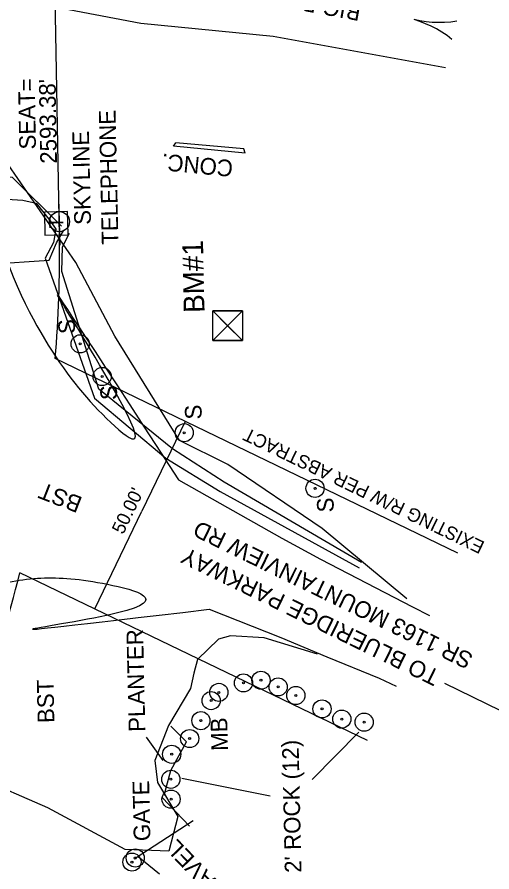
# Model space of a CAD drawing. Extents: x 1417249 to 1417944, y 999313 to 1000321.
# Drawn here: x 1417585 to 1417699.1, y 999696.9 to 999902.2 of the extents above; entities that cross this region are included whole.
import ezdxf

# ---------------------------------------------------------------- set-up
doc = ezdxf.new("R2010")
doc.units = 0
for name, color, linetype in [('CTL Bench Mark CELL', 7, 'Continuous'), ('CTL Bench Mark Text', 7, 'Continuous'), ('Exist Hydro Stream Flow Arrow CELL', 7, 'Continuous'), ('Exist Hydro Stream or Body of Water', 7, 'Continuous'), ('Exist Hydro Stream or Body of Water Text', 7, 'Continuous'), ('Exist Other Culture Area Outline', 7, 'Continuous'), ('Exist Other Culture Area Outline Leader', 7, 'Continuous'), ('Exist Other Culture Area Outline Text', 7, 'Continuous'), ('Exist Other Culture Gate', 7, 'Continuous'), ('Exist Other Culture Gate Text', 7, 'Continuous'), ('Exist Other Culture Located Object CELL', 7, 'Continuous'), ('Exist Other Culture Located Object Leader', 7, 'Continuous'), ('Exist Other Culture Located Object Text', 7, 'Continuous'), ('Exist Other Culture Sign CELL', 7, 'Continuous'), ('Exist Other Culture Sign Text', 7, 'Continuous'), ('Exist Right of Way Line', 7, 'Continuous'), ('Exist Right of Way Line Text', 7, 'Continuous'), ('Exist Right of Way Width CELL', 7, 'Continuous'), ('Exist Roads EOP', 7, 'Continuous'), ('Exist Roads EOP Leader', 7, 'Continuous'), ('Exist Roads EOP Other', 7, 'Continuous'), ('Exist Roads EOP Other Text', 7, 'Continuous'), ('Exist Roads EOP Text', 7, 'Continuous'), ('Exist Roads Soil', 7, 'Continuous'), ('Exist Roads Soil Text', 7, 'Continuous'), ('Exist Structure Major Bridge Seat Top Elevation', 7, 'Continuous'), ('Exist Utilities Telephone Pedestal CELL', 7, 'Continuous'), ('Exist Utilities Telephone Pole CELL', 7, 'Continuous'), ('Exist Utilities Telephone Pole Text', 7, 'Continuous'), ('Exist Utilities Telephone UG Cable SUE', 7, 'Continuous'), ('Exist Utilities Telephone UG FO SUE', 7, 'Continuous'), ('Exist Vegetation Woods Line', 7, 'Continuous')]:
    doc.layers.add(name, color=color, linetype=linetype)

msp = doc.modelspace()

# ---------------------------------------------------------------- linework, layer by layer
at = {"layer": 'CTL Bench Mark CELL'}
msp.add_line((1417635.6, 999828.12), (1417635.6, 999828.12), dxfattribs=at)
msp.add_lwpolyline([(1417632, 999831.71), (1417639.19, 999831.71), (1417639.19, 999824.52), (1417632, 999824.52)], close=True, dxfattribs=at)
for points in [[(1417639.19, 999831.71), (1417632, 999824.52), (1417635.59, 999828.11), (1417639.19, 999824.52), (1417632, 999831.71)], [(1417635.59, 999828.11), (1417639.19, 999831.71), (1417632, 999831.71), (1417635.59, 999828.11)], [(1417635.59, 999828.11), (1417632, 999824.52), (1417639.19, 999824.52), (1417635.59, 999828.11)]]:
    msp.add_lwpolyline(points, dxfattribs=at)
at = {"layer": 'Exist Hydro Stream Flow Arrow CELL'}
msp.add_line((1417685.21, 999900.36), (1417685.21, 999900.36), dxfattribs=at)
for points in [[(1417690.63, 999901.29), (1417689.18, 999901.05), (1417687.69, 999900.97), (1417686.21, 999900.91), (1417684.76, 999900.97), (1417683.29, 999901.11), (1417681.81, 999901.33), (1417680.38, 999901.64)], [(1417689.46, 999896.87), (1417688.32, 999897.79), (1417687.06, 999898.6), (1417685.81, 999899.39), (1417684.52, 999900.05), (1417683.17, 999900.65), (1417681.77, 999901.19), (1417680.38, 999901.64)]]:
    msp.add_lwpolyline(points, dxfattribs=at)
at = {"layer": 'Exist Hydro Stream or Body of Water'}
msp.add_lwpolyline([(1417489.18, 999956.86), (1417493.92, 999944.08), (1417519.87, 999911.97), (1417540.7, 999908.94), (1417551.94, 999906.04), (1417580.06, 999907.41), (1417614.71, 999900.78), (1417646.54, 999897.67), (1417687.93, 999890.16)], dxfattribs=at)
at = {"layer": 'Exist Other Culture Area Outline'}
msp.add_lwpolyline([(1417620.38, 999715.32), (1417621.97, 999721.32), (1417625.7, 999728.15), (1417621.97, 999731.9)], dxfattribs=at)
at = {"layer": 'Exist Other Culture Area Outline Leader'}
msp.add_lwpolyline([(1417620.08, 999723.72), (1417616.08, 999729.26)], dxfattribs=at)
at = {"layer": 'Exist Other Culture Gate'}
msp.add_lwpolyline([(1417613.4, 999700.26), (1417627.29, 999709.24)], dxfattribs=at)
at = {"layer": 'Exist Other Culture Located Object CELL'}
for centre, radius in [((1417639.4, 999742.32), 2.18), ((1417643.61, 999742.96), 2.18), ((1417639.4, 999742.32), 0.24), ((1417643.61, 999742.96), 0.24), ((1417647.73, 999741.36), 2.18), ((1417633.49, 999740.04), 2.18), ((1417647.73, 999741.36), 0.24), ((1417651.98, 999739.3), 2.18), ((1417631.63, 999738.07), 2.18), ((1417631.63, 999738.07), 0.24), ((1417633.49, 999740.04), 0.24), ((1417651.98, 999739.3), 0.24), ((1417658.27, 999736.07), 2.18), ((1417658.27, 999736.07), 0.24), ((1417629.17, 999733.25), 2.18), ((1417663.02, 999733.62), 2.18), ((1417668.39, 999732.89), 2.18), ((1417629.17, 999733.25), 0.24), ((1417663.02, 999733.62), 0.24), ((1417668.39, 999732.89), 0.24), ((1417626.47, 999728.95), 2.18), ((1417626.47, 999728.95), 0.24), ((1417621.95, 999719.17), 2.18), ((1417621.95, 999719.17), 0.24), ((1417622, 999714.39), 2.18), ((1417622, 999714.39), 0.24), ((1417613.4, 999700.26), 2.18), ((1417613.4, 999700.26), 0.24)]:
    msp.add_circle(centre, radius, dxfattribs=at)
at = {"layer": 'Exist Other Culture Located Object Leader'}
for points in [[(1417667.13, 999730.5), (1417655.91, 999719.13)], [(1417624.6, 999719.4), (1417645.82, 999715.19)]]:
    msp.add_lwpolyline(points, dxfattribs=at)
at = {"layer": 'Exist Other Culture Sign CELL'}
for centre, radius in [((1417600.16, 999823.75), 2.18), ((1417600.16, 999823.75), 0.24), ((1417605.45, 999815.91), 2.18), ((1417605.45, 999815.91), 0.24), ((1417625.17, 999802.41), 2.18), ((1417625.17, 999802.41), 0.24), ((1417656.6, 999789.05), 2.18), ((1417656.6, 999789.05), 0.24), ((1417622.15, 999725.18), 2.18), ((1417622.15, 999725.18), 0.24), ((1417612.61, 999699.28), 2.18), ((1417612.61, 999699.28), 0.24)]:
    msp.add_circle(centre, radius, dxfattribs=at)
at = {"layer": 'Exist Right of Way Line'}
for p, q in [((1417595.19, 999849.65), (1417593.19, 999964.5)), ((1417690.92, 999773.5), (1417594.18, 999820.2)), ((1417669.18, 999728.47), (1417585.7, 999768.77))]:
    msp.add_line(p, q, dxfattribs=at)
for start, end in [(355.3705, 0.7286), (333.907, 345.8853)]:
    msp.add_arc((1417280.02, 999845.64), 315.19, start, end, dxfattribs=at)
at = {"layer": 'Exist Right of Way Width CELL'}
for p in [(1417625.38, 999805.14), (1417603.65, 999760.11)]:
    msp.add_line(p, (1417614.98, 999783.6), dxfattribs=at)
at = {"layer": 'Exist Roads EOP'}
for points in [[(1417623.78, 999791.13), (1417648.65, 999777.08), (1417657.87, 999772.05), (1417680.02, 999760.58), (1417684.09, 999758.52)], [(1417631.14, 999759.99), (1417648.39, 999753.24), (1417659.44, 999748.58), (1417671.98, 999743.45), (1417676.11, 999741.5)], [(1417657.17, 999749.26), (1417644.36, 999753.18), (1417636.32, 999753.63), (1417633.36, 999752.85), (1417628.34, 999747.97), (1417627.51, 999744.62), (1417626.64, 999741.01), (1417621.38, 999732.08), (1417618.13, 999723.71), (1417618.76, 999718.4), (1417623.59, 999710.2), (1417621.5, 999701.87), (1417610.96, 999702.3), (1417592.37, 999712.28), (1417575.45, 999719.66), (1417563.02, 999722.02), (1417554.96, 999720.26), (1417543.34, 999711.65)]]:
    msp.add_lwpolyline(points, dxfattribs=at)
for points in [[(1417575.63, 999865.05), (1417581.75, 999843.36), (1417591.73, 999822.61), (1417605.87, 999805.34), (1417623.78, 999791.13), (1417575.63, 999865.05), (1417623.78, 999791.13)], [(1417560.92, 999751.8), (1417567.38, 999759.55), (1417576.89, 999765.72), (1417590.73, 999768.05), (1417604.66, 999766.99), (1417631.14, 999759.99), (1417560.92, 999751.8), (1417631.14, 999759.99)]]:
    msp.add_open_spline(points, degree=3, dxfattribs=at)
at = {"layer": 'Exist Roads EOP Leader'}
msp.add_lwpolyline([(1417701.21, 999735.58), (1417687.79, 999742.14)], dxfattribs=at)
at = {"layer": 'Exist Roads EOP Other'}
for points in [[(1417639.82, 999869.57), (1417622.61, 999871.22), (1417623.16, 999872.07)], [(1417639.82, 999869.57), (1417639.45, 999870.58), (1417623.16, 999872.07)]]:
    msp.add_lwpolyline(points, dxfattribs=at)
at = {"layer": 'Exist Roads Soil'}
for p, q in [((1417626.45, 999707.94), (1417619.83, 999714.79)), ((1417614.08, 999700.65), (1417619.22, 999696.44))]:
    msp.add_line(p, q, dxfattribs=at)
at = {"layer": 'Exist Utilities Telephone Pedestal CELL'}
msp.add_line((1417594.41, 999852.62), (1417594.41, 999852.62), dxfattribs=at)
msp.add_lwpolyline([(1417597.3, 999849.96), (1417597.16, 999855.55), (1417591.57, 999855.42), (1417591.7, 999849.83), (1417597.3, 999849.96)], dxfattribs=at)
at = {"layer": 'Exist Utilities Telephone Pole CELL'}
for p, q in [((1417595.33, 999847.43), (1417595.06, 999858.76)), ((1417595.19, 999853.1), (1417595.19, 999853.1))]:
    msp.add_line(p, q, dxfattribs=at)
msp.add_circle((1417595.19, 999853.1), 2.41, dxfattribs=at)
at = {"layer": 'Exist Utilities Telephone UG Cable SUE'}
msp.add_lwpolyline([(1417541.97, 999869.57), (1417546.14, 999867.98), (1417547.57, 999867.07), (1417556.49, 999859.36), (1417574.93, 999859.01), (1417586.41, 999858.26), (1417589.59, 999857.53), (1417592.95, 999853.3), (1417594.32, 999851.29), (1417593.73, 999848.07), (1417591.79, 999844.34), (1417603.62, 999810.67), (1417620.71, 999796.33), (1417633.83, 999788.28), (1417667.2, 999769.98)], dxfattribs=at)
at = {"layer": 'Exist Utilities Telephone UG FO SUE'}
for points in [[(1417541.38, 999869.29), (1417557.07, 999863.91), (1417575.14, 999864.61), (1417583.79, 999863.82), (1417595.69, 999852.02)], [(1417467.59, 999656.83), (1417499.73, 999689.79), (1417522.28, 999727.87), (1417539.9, 999771.2), (1417542.88, 999787.94), (1417546.19, 999818.6), (1417546.93, 999839.08), (1417547.54, 999844.95), (1417549.16, 999846.16), (1417559.4, 999845.4), (1417578.31, 999842.88), (1417592.74, 999843.86), (1417594.44, 999847.99), (1417596.21, 999851.03)], [(1417667.72, 999771.26), (1417634.73, 999790.53), (1417622.34, 999798.55), (1417604.69, 999812.85), (1417595.77, 999841.15), (1417595.91, 999847.06), (1417597.63, 999850.35)]]:
    msp.add_lwpolyline(points, dxfattribs=at)
at = {"layer": 'Exist Vegetation Woods Line'}
msp.add_lwpolyline([(1417678.64, 999762.53), (1417658.28, 999779.42), (1417635.66, 999794.75), (1417624, 999800.57), (1417608.51, 999825.62), (1417599.15, 999843.27), (1417580.46, 999870.2)], dxfattribs=at)

# ---------------------------------------------------------------- texts
at = {"layer": 'CTL Bench Mark Text'}
msp.add_text('BM#1', height=5, rotation=91.2799, dxfattribs=at).set_placement((1417630.06, 999831.24))
at = {"layer": 'Exist Hydro Stream or Body of Water Text'}
msp.add_text('BIG PINE CREEK', height=4, rotation=169.7146, dxfattribs=at).set_placement((1417667.89, 999905.21))
at = {"layer": 'Exist Other Culture Area Outline Text'}
msp.add_text('PLANTER', height=4, rotation=91.2799, dxfattribs=at).set_placement((1417615.83, 999730.6))
at = {"layer": 'Exist Other Culture Gate Text'}
msp.add_text('GATE', height=4, rotation=91.2799, dxfattribs=at).set_placement((1417617.05, 999704.36))
at = {"layer": 'Exist Other Culture Located Object Text'}
msp.add_text("2' ROCK (12)", height=4, rotation=91.2799, dxfattribs=at).set_placement((1417653.34, 999696.76))
at = {"layer": 'Exist Other Culture Sign Text'}
for s, p in [('S', (1417598.96, 999826.15)), ('S', (1417609.06, 999810.3)), ('S', (1417629.39, 999805.62)), ('S', (1417661.11, 999783.31)), ('MB', (1417635.67, 999726.04))]:
    msp.add_text(s, height=4, rotation=91.2799, dxfattribs=at).set_placement(p)
at = {"layer": 'Exist Right of Way Line Text'}
msp.add_text('EXISTING R/W PER ABSTRACT', height=3.2, rotation=154.2319, dxfattribs=at).set_placement((1417697.58, 999776.08))
at = {"layer": 'Exist Right of Way Width CELL'}
msp.add_text("50.00'", height=3.2, rotation=64.2319, dxfattribs=at).set_placement((1417610.5, 999777.81))
at = {"layer": 'Exist Roads EOP Other Text'}
msp.add_text('CONC.', height=4, rotation=174.5244, dxfattribs=at).set_placement((1417637.05, 999867.82))
at = {"layer": 'Exist Roads EOP Text'}
for s, rotation, p in [('BST', 158.638, (1417600.96, 999786.78)), ('SR 1163 MOUNTAINVIEW RD', 153.9552, (1417694.88, 999749.08)), ('TO BLUERIDGE PARKWAY', 153.9552, (1417686.89, 999745.09)), ('BST', 91.2799, (1417593.98, 999732.72))]:
    msp.add_text(s, height=4, rotation=rotation, dxfattribs=at).set_placement(p)
at = {"layer": 'Exist Roads Soil Text'}
msp.add_text('GRAVEL', height=4, rotation=134.026, dxfattribs=at).set_placement((1417638.49, 999689.44))
at = {"layer": 'Exist Structure Major Bridge Seat Top Elevation'}
for s, p in [('SEAT=', (1417589.54, 999870.46)), ("2593.38'", (1417594.6, 999867.05))]:
    msp.add_text(s, height=4, rotation=90.9888, dxfattribs=at).set_placement(p)
at = {"layer": 'Exist Utilities Telephone Pedestal CELL'}
msp.add_text('T', height=3.42, rotation=91.3853, dxfattribs=at).set_placement((1417596.15, 999851.53))
at = {"layer": 'Exist Utilities Telephone Pole Text'}
for s, p in [('TELEPHONE', (1417609.38, 999847.6)), ('SKYLINE', (1417602.77, 999852.37))]:
    msp.add_text(s, height=4, rotation=91.2799, dxfattribs=at).set_placement(p)

doc.saveas('drawing.dxf')
